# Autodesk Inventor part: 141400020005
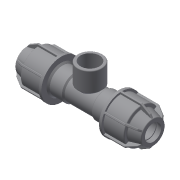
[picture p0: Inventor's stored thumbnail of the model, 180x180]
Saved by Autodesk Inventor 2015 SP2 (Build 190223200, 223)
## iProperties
Created: 2017-08
Part Number: 141400020005
Material: Generic
Description: PLASSON L.14 TEE FEMALE ADAPTOR (SILVER) 20 x 1/2" x 20
Document SubType Name: Modeling
Designer: KIM
Density: 1 g/cm^3
Appearance: Default
Author: KIM
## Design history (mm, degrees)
derived "141400.ipt"
feature "Solid1::141400.ipt"
feature "Solid2::141400.ipt"
tag "TaggingFeature1"
body "Solid1"
other parameters: "d2" = 44, "d4" = 15 deg, "d5" = 29.04, "d6" = 9.5832, "d10" = 42, "d16" = 20.4, "d17" = 2.2, "d22" = 32, "d24" = 2.2, "d25" = 37.8, "d26" = 31.5, "d27" = 2.2, "d28" = 135 deg, "d29" = 1.32, "d31" = 1, "d46" = 150 deg, "d49" = 2.1, "d50" = 0, "d58" = 0.6, "d61" = 360 deg, "d63" = 18, "d64" = 56.5, "d80" = 28.8, "d81" = 1.6, "d84" = 2.2, "d94" = 43, "d95" = 18.631, "d96" = 24.2203, "d97" = 18, "d98" = 16, "d99" = 20.58726, "d100" = 135 deg, "d108" = 1, "d111" = 0, "G_" = 18.631, "E_" = 42, "H_" = 113, "l_" = 44, "l_2" = 18, "A_" = 43
